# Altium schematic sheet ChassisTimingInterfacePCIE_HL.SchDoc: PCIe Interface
size B; Engineer: Daniel Sigg; DocumentNumber: 1; Revision: C; SheetNumber: 11; SheetTotal: 12; PageSetup: Record=PageOptions¦CenterHorizontal=True¦CenterVertical=True¦PrintScale=0.72¦XCorrection=1.00¦YCorrection=1.00¦PrintKind=0¦BorderSize=5000000¦LeftOffset=0¦BottomOffset=0¦Orientation=2¦PaperLength=1000¦PaperWidth=1000¦Scale=100¦PaperSource=7¦PrintQuality=-4¦MediaType=1¦DitherType=10¦PaperKind=Tabloid¦PrintScaleMode=1
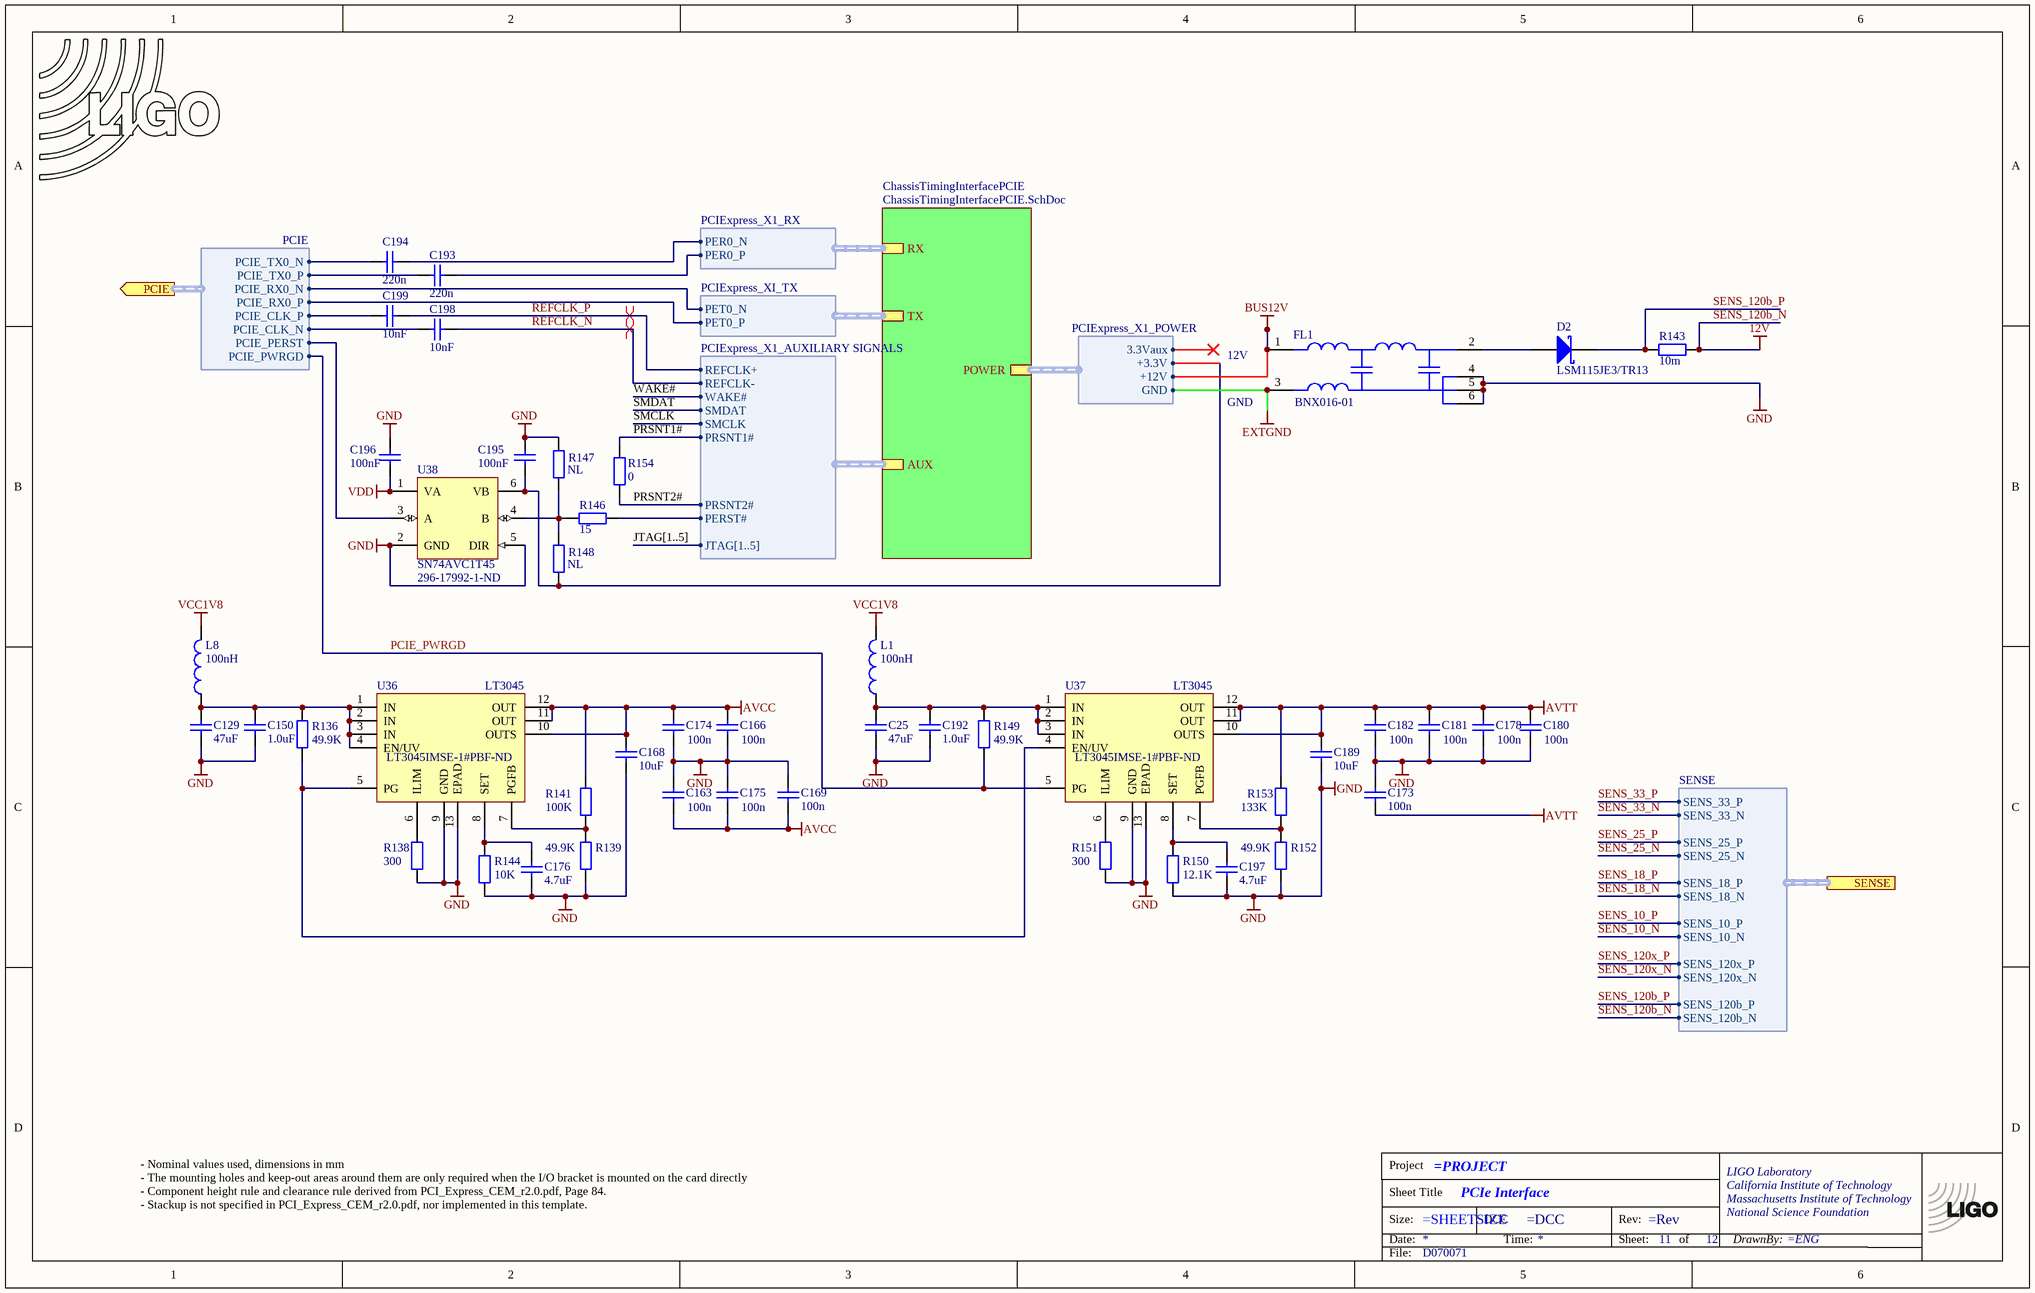
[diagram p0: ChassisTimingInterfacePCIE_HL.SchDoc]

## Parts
*?  TitleBlock  (value not drawn)  (graphical)
C25  47uF  [CC3216-1206]
C129  47uF  [CC3216-1206]
C150  1.0uF  [CC1608-0603]
C163  100n  [CAPC0603X33X15NL03T05]
C166  100n  [CAPC0603X33X15NL03T05]
C168  10uF  [CC2013-0805]
C169  100n  [CAPC0603X33X15NL03T05]
C173  100n  [CAPC0603X33X15NL03T05]
C174  100n  [CAPC0603X33X15NL03T05]
C175  100n  [CAPC0603X33X15NL03T05]
C176  4.7uF  [CC1608-0603]
C178  100n  [CAPC0603X33X15NL03T05]
C180  100n  [CAPC0603X33X15NL03T05]
C181  100n  [CAPC0603X33X15NL03T05]
C182  100n  [CAPC0603X33X15NL03T05]
C189  10uF  [CC2013-0805]
C192  1.0uF  [CC1608-0603]
C193  220n  [CC1005-0402]
C194  220n  [CC1005-0402]
C195  100nF  [CC1005-0402]
C196  100nF  [CC1005-0402]
C197  4.7uF  [CC1608-0603]
C198  10nF  [CC1005-0402]
C199  10nF  [CC1005-0402]
D2  LSM115JE3/TR13  [MCSM-DO-214BA-2_L]
FL1  BNX016-01  [MURA-BNX016-01_V]
L1  100nH  [CL2520-1008]
L8  100nH  [CL2520-1008]
LOGO?  LIGO logo  [LIGO_LOGO]  (value not drawn)  (graphical)
R136  49.9K  [CR1005-0402]
R138  300  [CR1005-0402]
R139  49.9K  [CR1005-0402]
R141  100K  [CR1005-0402]
R143  10m  [CC3216-1206]
R144  10K  [CR1005-0402]
R146  15  [CR1005-0402]
R147  NL  [CR1005-0402]
R148  NL  [CR1005-0402]
R149  49.9K  [CR1005-0402]
R150  12.1K  [CR1005-0402]
R151  300  [CR1005-0402]
R152  49.9K  [CR1005-0402]
R153  133K  [CR1005-0402]
R154  0  [CR1005-0402]
U36  LT3045  Supplier Part Number 1: LT3045IMSE-1#PBF-ND  [MSOP12_PAD]
U37  LT3045  Supplier Part Number 1: LT3045IMSE-1#PBF-ND  [MSOP12_PAD]
U38  SN74AVC1T45  Supplier Part Number 1: 296-17992-1-ND  [SC70]

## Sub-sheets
ChassisTimingInterfacePCIE = ChassisTimingInterfacePCIE.SchDoc: RX (harness PCIExpress_X1_RX), TX (harness PCIExpress_XI_TX), AUX (harness PCIExpress_X1_AUXILIARY SIGNALS), POWER (harness PCIExpress_X1_POWER)

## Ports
PCIE (out, harness PCIE), SENSE (harness SENSE)

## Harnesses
PCIExpress_X1_RX: PER0_N, PER0_P
PCIE: PCIE_CLK_N, PCIE_CLK_P, PCIE_RX0_N, PCIE_RX0_P, PCIE_TX0_N, PCIE_TX0_P, PCIE_PERST, PCIE_PWRGD
PCIExpress_XI_TX: PET0_N, PET0_P
PCIExpress_X1_POWER: +3.3V, +12V, GND, 3.3Vaux
PCIExpress_X1_AUXILIARY SIGNALS: JTAG[1..5], PERST#, PRSNT1#, PRSNT2#, REFCLK+, REFCLK-, SMCLK, SMDAT, WAKE#
SENSE: SENS_33_P, SENS_33_N, SENS_25_P, SENS_25_N, SENS_18_P, SENS_18_N, SENS_10_P, SENS_10_N, SENS_120x_P, SENS_120x_N, SENS_120b_P, SENS_120b_N

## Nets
AVCC: C163.1 C166.2 C168.2 C169.1 C174.2 C175.1 R141.2 U36.10(OUTS) U36.11(OUT) U36.12(OUT)
AVTT: C173.1 C178.2 C180.2 C181.2 C182.2 C189.2 R153.2 U37.10(OUTS) U37.11(OUT) U37.12(OUT)
BUS12V: FL1.1(B) ; sheet ChassisTimingInterfacePCIE/POWER.+12V
EXTGND: FL1.3(PSG) ; sheet ChassisTimingInterfacePCIE/POWER.GND
GND: C25.1 C129.1 C150.1 C163.2 C166.1 C168.1 C169.2 C173.2 C174.1 C175.2 C176.1 C178.1 C180.1 C181.1 C182.1 C189.1 C192.1 C195.2 C196.2 C197.1 FL1.4(CG) FL1.5(CG) FL1.6(CG) R138.1 R139.1 R144.1 R147.1 R150.1 R151.1 R152.1 U36.9(GND) U36.13(EPAD) U37.9(GND) U37.13(EPAD) U38.2(GND) U38.5(DIR)
SENS_120b_N: R143.2 ; port SENSE.SENS_120b_N  [also labelled 12V]
VCC1V8: L1.2 L8.2
VDD: C196.1 U38.1(VA)
PCIE_PWRGD: R149.1 U37.5(PG) ; port PCIE.PCIE_PWRGD
PRSNT1#: R154.2 ; sheet ChassisTimingInterfacePCIE/AUX.PRSNT1#
PRSNT2#: R154.1 ; sheet ChassisTimingInterfacePCIE/AUX.PRSNT2#
REFCLK_N: C198.1 ; sheet ChassisTimingInterfacePCIE/AUX.REFCLK-
REFCLK_P: C199.1 ; sheet ChassisTimingInterfacePCIE/AUX.REFCLK+
SENS_120b_P: D2.2(K) R143.1 ; port SENSE.SENS_120b_P
NetC25_2: C25.2 C192.2 L1.1 R149.2 U37.1(IN) U37.2(IN) U37.3(IN)
NetC129_2: C129.2 C150.2 L8.1 R136.2 U36.1(IN) U36.2(IN) U36.3(IN) U36.4(EN/UV)
NetC176_2: C176.2 R144.2 U36.8(SET)
NetC193_1: C193.1 ; sheet ChassisTimingInterfacePCIE/RX.PER0_P
NetC193_2: C193.2 ; port PCIE.PCIE_TX0_P
NetC194_1: C194.1 ; sheet ChassisTimingInterfacePCIE/RX.PER0_N
NetC194_2: C194.2 ; port PCIE.PCIE_TX0_N
NetC195_1: C195.1 R148.2 U38.6(VB) ; sheet ChassisTimingInterfacePCIE/POWER.+3.3V
NetC197_2: C197.2 R150.2 U37.8(SET)
NetC198_2: C198.2 ; port PCIE.PCIE_CLK_N
NetC199_2: C199.2 ; port PCIE.PCIE_CLK_P
NetD2_1: D2.1(A) FL1.2(CB)
NetR136_1: R136.1 U36.5(PG) U37.4(EN/UV)
NetR138_2: R138.2 U36.6(ILIM)
NetR139_2: R139.2 R141.1 U36.7(PGFB)
NetR146_1: R146.1 ; sheet ChassisTimingInterfacePCIE/AUX.PERST#
NetR146_2: R146.2 R147.2 R148.1 U38.4(B)
NetR151_2: R151.2 U37.6(ILIM)
NetR152_2: R152.2 R153.1 U37.7(PGFB)
NetU38_3: U38.3(A) ; port PCIE.PCIE_PERST
(unnamed): port PCIE.PCIE_RX0_N, sheet ChassisTimingInterfacePCIE/TX.PET0_N
(unnamed): port PCIE.PCIE_RX0_P, sheet ChassisTimingInterfacePCIE/TX.PET0_P  [a separate net that carries the same name]

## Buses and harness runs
bus JTAG[1..5]

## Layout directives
differential pair: REFCLK_N, REFCLK_P

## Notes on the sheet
- (near FL1) 12V
- (near FL1) GND
- - Nominal values used, dimensions in mm
  - The mounting holes and keep-out areas around them are only required when the I/O bracket is mounted on the card directly
  - Component height rule and clearance rule derived from PCI_Express_CEM_r2.0.pdf, Page 84.
  - Stackup is not specified in PCI_Express_CEM_r2.0.pdf, nor implemented in this template.

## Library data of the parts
C25 C129 = ChipCap: C1206 47uF; Part Number: 490-16268-1-ND; Tolerance: 10%
C150 C192 = ChipCap: C0603 1.0uF; Part Number: 1276-1184-1-ND; Tolerance: 10%
C163 C166 C169 C173-C175 C178 C180-C182 = CMP-2010-00306-1: C0201 0.1uF; Part Number: CL03A474MR3NNNC; Tolerance: 10%
C168 C189 = ChipCap: C0805 10uF; Part Number: 1276-6454-1-ND; Tolerance: 10%
C176 C197 = ChipCap: C0603 4.7uF; Part Number: 1276-2087-1-ND; Tolerance: 10%
C193 C194 = ChipCap: C0402 0.22uF; Part Number: 587-6021-1-ND; Tolerance: 10%
C195 C196 = ChipCap: C0402 0.1uF; Part Number: 1276-6720-1-ND; Tolerance: 10%
C198 C199 = ChipCap: C0402 0.01uF; Part Number: 311-1349-1-ND; Tolerance: 10%
D2 = CMP-2000-06604-1: Ultra Low Forward Voltage Schottky Rectifier, 15 V, -55 to 100 degC, 2-Pin Molded, RoHS, Tape and Reel; Part Number: LSM115JE3/TR13CT-ND
FL1 = CMP-2000-05960-1: Block Type EMIFIL(R) Reference Specification, 15 A, 25 V, -40 to 125 degC, 6-Pin THD, RoHS, Bulk; Part Number: 490-5055-ND
L1 L8 = ChipInductor: Inductor; Part Number: 994-1008CS-101XJLC
LOGO? = LIGO_logo
R136 R139 R149 R152 = ChipRes1: R0402 49.9k; Part Number: RR05P49.9KDCT-ND; Tolerance: 0.1%
R138 R151 = ChipRes1: R0402 300; Part Number: RR05P300DCT-ND; Tolerance: 0.1%
R141 = ChipRes1: R0402 100k; Part Number: RR05P100KDCT-ND; Tolerance: 0.1%
R143 = ChipRes1: R1206 10m; Part Number: 273-PCS1206DR0100ETCT-ND; Tolerance: 0.1%
R144 = ChipRes1: R0402 10k; Part Number: RR05P10.0KDCT-ND; Tolerance: 0.1%
R146 = ChipRes1: R0402 15; Part Number: A127144CT-ND; Tolerance: 0.1%
R147 R148 = ChipRes1: Resistor, surface mount; Tolerance: 0.1%
R150 = ChipRes1: R0402 12.1k; Part Number: RR05P12.1KDCT-ND; Tolerance: 0.1%
R153 = ChipRes1: R0402 133k; Part Number: A127523CT-ND; Tolerance: 0.1%
R154 = ChipRes1: R0402 0; Part Number: 541-2877-1-ND; Tolerance: 0.1%
U36 U37 = LT3045: 20V, 500mA, Ultralow Noise, / Ultrahigh PSRR Linear Regulator
U38 = SN74LVC1T45: Single-Bit Dual Supply Transceiver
